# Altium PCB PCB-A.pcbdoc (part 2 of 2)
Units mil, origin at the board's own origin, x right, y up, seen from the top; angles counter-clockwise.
Board outline 4955 x 3850 mil, 4 copper layers (Top Layer, Inner1, Inner2, Bottom Layer); 128 components, 159 nets, 685 pads, 359 vias.
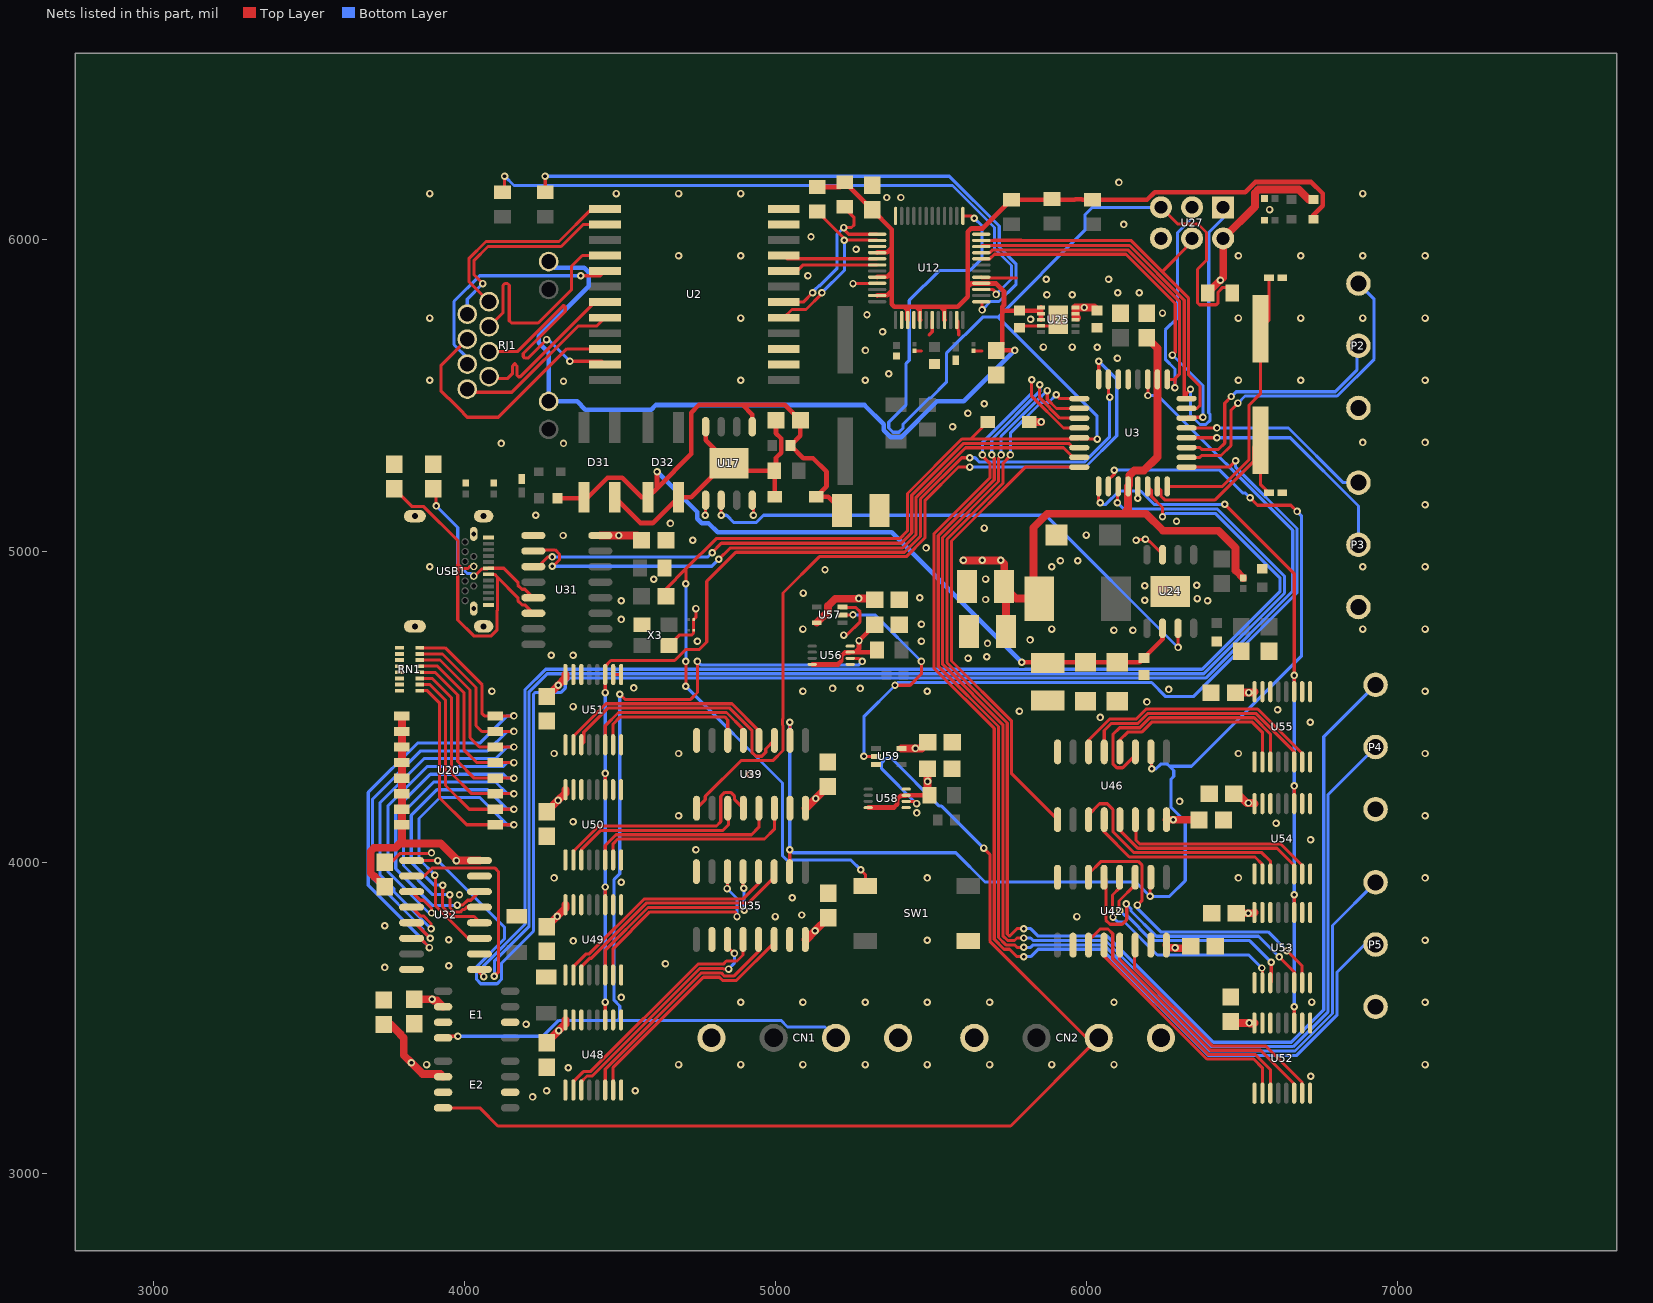
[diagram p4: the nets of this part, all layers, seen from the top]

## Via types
v1: diameter 24, hole 12, Top Layer to Bottom Layer, 345 vias
v2: diameter 24.02, hole 12.01, Top Layer to Bottom Layer, 14 vias

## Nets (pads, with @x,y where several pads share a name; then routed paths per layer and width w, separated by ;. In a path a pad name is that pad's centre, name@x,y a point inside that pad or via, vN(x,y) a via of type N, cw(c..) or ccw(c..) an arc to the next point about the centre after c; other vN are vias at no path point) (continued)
+5V: C25.1 C30.1 C34.2 C60.2 C61.2 C67.2 C78.1 C79.2 C80.2 C81.1 C82.1 C83.1 C84.1 C85.1 C86.2 C87.2 C88.1 C89.1 C90.1 C91.1 C93.1 C94.2 C96.1 C97.2 CN1.4 CN2.4 D35.1 E1.2 E2.2 L2.2 LED5.2 R36.1 R52.2 R69.1 R71.1 U3.4 U3.18 U20.9 U20.10 U20.11 U20.12 U20.13 U20.14 U20.15 U20.16 U25.8 U25.9 U25.10 U27.2 U31.16 U32.16 U35.16 U39.16 U42.16 U46.16 U48.16 U49.16 U50.16 U51.16 U52.16 U53.16 U54.16 U55.16 U56.3 U56.8 U57.5 U58.3 U58.8 U59.5 | length 6394.9
  Top Layer w15: U56.8@5118.98,4635.47 5201.65,4635.47 5212.76,4646.58 5212.76,4662.79 5223.55,4673.58 5239.77,4673.58 U56.3@5241.02,4674.84 5257.23,4674.84 ; U58.8@5298.98,4175.47 5381.65,4175.47 5392.76,4186.58 5392.76,4202.79 5403.55,4213.58 5419.77,4213.58 U58.3@5421.02,4214.84 5421.21,4215.02 R71.1@5496.01,4215.02 ; C93.1@5319.91,4762.74 v1(5269.29,4712.13) 5269.29,4686.9 5257.23,4674.84 ; R69.1@5327.53,4682.11 5320.27,4674.84 5257.23,4674.84
  Top Layer w25: C87.2@3741.36,3477.9 3764.23,3477.9 3794.93,3447.2 3794.93,3445.21 3805.76,3434.37 3805.76,3379.3 v1(3830.48,3354.58) 3866.47,3318.6 3923.53,3318.6 E2.2@3932.13,3310 ; C34.2@3744.79,3920.98 3712.31,3953.47 3710.55,3953.47 3699.72,3964.31 3699.72,4035.14 3710.55,4045.98 3779.03,4045.98 3793.05,4060 ; U20.9@3800,4470 U20.10@3800,4420 U20.11@3800,4370 U20.12@3800,4320 U20.13@3800,4270 U20.14@3800,4220 U20.15@3800,4170 U20.16@3800,4120 3800,4066.95 3793.05,4060 ; C80.2@3840,3559.37 v1(3896.78,3559.37) 3901.46,3554.69 3912.44,3554.69 E1.2@3932.13,3535 ; U32.16@4049.02,4005 v1(3975.01,4005) 3975.01,4010 3925.01,4060 3793.05,4060 ; C81.1@4265,3419.37 v1(4304.08,3458.45) 4325.43,3479.8 U48.16@4325.43,3492.82 ; C82.1@4265.66,3791.9 v1(4299.19,3825.42) 4325.43,3851.66 U49.16@4325.43,3862.82 ; C83.1@4265.66,4162.1 v1(4301.86,4198.3) 4325.43,4221.87 U50.16@4325.43,4232.82 ; C84.1@4265.66,4532.3 v1(4302.09,4568.73) 4325.43,4592.07 U51.16@4325.43,4602.82 ; U31.16@4437.7,5050 v1(4496.56,5050) 4555.42,5050 C30.1@4570.42,5035 ; U35.16@5096.58,3751.35 5100.35,3751.35 v1(5127.95,3778.96) C78.1@5170,3821 ; U39.16@5097.31,4173.26 5099.24,4173.26 v1(5130.44,4204.47) C79.2@5168.89,4242.91 ; U57.5@5133.66,4769.41 5170,4805.75 5170,4824.04 5192.93,4846.96 5267.79,4846.96 v1(5268.57,4847.74) 5315.21,4847.74 C94.2@5320.21,4842.74 ; U59.5@5406.34,4365.59 v1(5450.87,4365.59) 5471.22,4365.59 C97.2@5490.63,4385 ; C96.1@5489.82,4300.66 v1(5489.82,4259.21) 5489.82,4221.22 R71.1@5496.01,4215.02 ; v1(5605,4970) v1(5665.43,4970) v1(5725,4970) 5736.01,4958.99 C61.2@5736.01,4886.37 ; C60.2@5742.09,4741.37 5742.09,4880.29 5775.25,4847.13 L2.2@5849.15,4847.13 5830,4866.28 5830,5075 5875,5120 6120.69,5120 ; D35.1@5816.93,5415 v1(5855,5415) ; 5970,5750 5965.57,5754.43 U25.9@5965.57,5763.24 U25.10@5965.57,5782.93 v1(5993.68,5782.93) 6024.96,5782.93 C67.2@6035,5772.89 ; C25.1@6195,5685.63 6228.74,5651.89 U3.18@6228.74,5552 6228.74,5302.49 6185.23,5258.98 6154.42,5258.98 6138.39,5242.95 6138.39,5212.14 U3.4@6134.25,5208 6134.25,5133.57 6120.69,5120 ; U42.16@6257.31,3733.26 6266.01,3724.56 v1(6285.5,3724.56) 6287.05,3723.02 6328.65,3723.02 C85.1@6335.63,3730 ; U46.16@6257.68,4136.35 v1(6279.77,4136.35) 6361.46,4136.35 C86.2@6362.44,4135.37 ; R36.1@6390.63,5830 v1(6431.14,5870.51) 6440,5879.37 U27.2@6440,6005 6542.6,6107.6 6542.6,6151.46 6553.43,6162.3 6683.11,6162.3 6715.39,6130.02 LED5.2@6730.57,6130.02 ; C91.1@6474.37,4220 6486.29,4220 v1@6516.29,4190 ; C88.1@6479.11,3481.65 6480.29,3482.82 v1(6523.66,3482.82) 6525.72,3480.76 6538.37,3480.76 U52.16@6540.43,3482.82 ; C90.1@6479.37,4545 v1(6522.05,4545) 6537.6,4545 U55.16@6540.43,4547.82 ; C89.1@6482.4,3835.37 v1(6520.72,3835.37) 6537.98,3835.37 U53.16@6540.43,3837.82 ; R52.2@6504.78,4913.09 6480.07,4937.8 6480.07,5009.79 6424.86,5065 6246.87,5065 6191.87,5120 6120.69,5120 ; v1(6521.29,4190) 6538.26,4190 U54.16@6540.43,4187.82
+33V: C32.1 C33.1 C66.2 LED6.2 R38.2 R39.2 R40.2 R60.2 R61.2 RJ1.9 RJ1.11 U12.4 U12.8 U12.11 U12.15 U12.17 U12.21 U12.28 U25.1 U25.2 U25.3 | length 5527.4
  Top Layer w15: R60.2@5134.87,6170.49 5208.47,6170.49 R61.2@5223.47,6185.49 5311.55,6097.42 C33.1@5311.55,6097.22 5375,6033.76 5375,5975.4 ; U12.11@5327.68,5821.42 5328.55,5822.28 5359.69,5822.28 5375,5837.6 ; U12.8@5327.68,5880.47 5328.56,5881.35 5359.69,5881.35 5375,5896.66 ; U12.4@5327.68,5959.21 5328.56,5960.09 5359.69,5960.09 5375,5975.4 ; U12.15@5426.1,5742.68 5425.23,5743.55 5425.23,5774.69 5414.21,5785.71 ; U12.17@5465.47,5742.68 5464.6,5743.55 5464.6,5774.69 5453.58,5785.71 ; U12.21@5544.21,5742.68 5543.35,5743.55 5543.35,5774.69 5532.32,5785.71 ; U12.28@5662.32,5860.79 U12.28@5661.44,5859.91 ; C32.1@5710,5644.37 C32.1@5710.63,5645 ; v1(5770,5645) C32.1@5710.63,5645 ; U25.3@5854.43,5743.56 U25.2@5854.43,5763.24 U25.1@5854.43,5782.93 5844.39,5772.89 C66.2@5785,5772.89 5730,5772.89 ; LED6.2@6730.57,6066.15 6730.57,6081.4 6759.82,6110.65 6759.82,6149.39 6722.91,6186.3 6543.49,6186.3 6511.13,6153.93 6219.73,6153.93 6195.17,6129.37 R40.2@6020,6129.37 5986.93,6129.37 5985.47,6130.83 5964.34,6130.83 5962.88,6129.37 5759.37,6129.37 R38.2@5759.25,6129.25 5667.08,6037.09 5630.31,6037.09 5619.29,6026.06 5619.29,5848.89 ; 5375,5837.6 5375,5896.66 ; 5375,5837.6 5375,5793.78 5383.07,5785.71 5414.21,5785.71 ; 5375,5896.66 5375,5975.4 ; 5414.21,5785.71 5453.58,5785.71 ; 5453.58,5785.71 5532.32,5785.71 ; 5532.32,5785.71 5587.24,5785.71 5619.29,5817.76 5619.29,5848.89 ; 5619.29,5848.89 5630.31,5859.91 U12.28@5661.44,5859.91 ; U12.28@5661.44,5859.91 5710.99,5859.91 5735.35,5835.56 5735.35,5790.9 5730,5785.55 5730,5772.89 ; C32.1@5710.63,5645 5730,5664.37 5730,5772.89
  Bottom Layer w15: RJ1.9@4271.77,5930.67 4291.93,5910.51 4385.57,5910.51 4400.51,5895.57 4400.51,5851.58 4239.49,5690.57 4239.49,5669.43 4271.76,5637.16 RJ1.11@4271.77,5481.07 4362.87,5481.07 4389.44,5454.5 4601.34,5454.5 4616.28,5469.44 5286.8,5469.44 5348.54,5407.69 5348.54,5388.64 5371.68,5365.5 5404.4,5365.5 5519.97,5481.07 5606.07,5481.07 v1(5770,5645)
A0: U3.23 U48.11 U49.11 U50.11 U51.11 | length 3555.6
  Top Layer w10: U48.11@4453.39,3492.82 v1(4453.39,3550) ; U49.11@4453.39,3862.82 v1(4453.39,3920) ; U50.11@4453.39,4232.82 v1(4453.39,4285) ; v1(4453.39,4545) U51.11@4453.39,4602.82 4453.39,4629.67 4471.63,4647.91 4676.42,4647.91 4711.8,4683.29 4755.82,4683.29 4780,4707.47 4780,4902.52 4873.48,4996 5415.4,4996 5467,5047.6 5467,5167.6 5599.4,5300 v1(5625,5300) ; U3.23@6071.26,5552 6071.26,5498.74 v1(6075,5495)
  Bottom Layer w10: v1(4453.39,3550) v1(4453.39,3920) v1(4453.39,4285) v1(4453.39,4545) ; v1(5625,5300) 5642.47,5300 5656.47,5286 5993.53,5286 6075,5367.47 v1(6075,5495)
A1: U3.24 U39.9 | length 2542.3
  Top Layer w10: U39.9@4747.31,4173.26 4775.01,4200.96 4775.01,4211.32 4889.87,4326.18 4992.54,4326.18 5025,4358.64 5025,4439.05 5023.58,4440.47 5023.58,4459.53 5025,4460.95 5025,4865 5142,4982 5421.2,4982 5481,5041.8 5481,5161.8 5589.2,5270 v1(5625,5270) ; U3.24@6039.76,5552 6040,5552.24 v1(6040,5610)
  Bottom Layer w10: v1(5625,5270) 5997.33,5270 6098,5370.67 6098,5552 v1(6040,5610)
A2: P4.3 U3.25 | length 4391
  Top Layer w10: v1(5756,5309) 5756,5306.47 5732,5282.47 5732,5217.6 5552,5037.6 5552,4641.33 5745.93,4447.4 5745.93,3769.07 5753,3762 5777,3786 v1(5799,3786) ; v1(5903,5502.06) 5915.05,5490 5977.26,5490 U3.25@5977.5,5490.24
  Bottom Layer w10: v1(5756,5309) 5756,5379 5854.48,5477.48 5878.42,5477.48 v1(5903,5502.06) ; v1(5799,3786) 5821,3786 5845,3762 6067.4,3762 6408.57,3420.83 6659.17,3420.83 6763.34,3525 6763.34,4403.34 P4.3@6930,4570
A3: P4.2 U3.26 | length 4277.4
  Top Layer w10: v1(5726,5309) 5726,5306.47 5718,5298.47 5718,5223.4 5538,5043.4 5538,4635.53 5731.93,4441.6 5731.93,3763.27 5747.2,3748 5769,3748 5777,3756 v1(5799,3756) ; v1(5874.56,5516.04) 5874.56,5487.57 5904.07,5458.06 5944.91,5458.06 5945.59,5458.74 U3.26@5977.5,5458.74
  Bottom Layer w10: v1(5726,5309) 5726,5368.8 5848.68,5491.48 5850.1,5491.48 5863.57,5504.96 5863.57,5505.06 v1(5874.56,5516.04) ; v1(5799,3756) 5821,3756 5829,3748 6061.6,3748 6402.77,3406.83 6664.97,3406.83 6777.34,3519.2 6777.34,3731.6 ; 6777.4,3731.66 6777.4,4217.4 P4.2@6930,4370
A4: P5.3 U3.27 | length 3956.1
  Top Layer w10: v1(5696,5309) 5696,5306.47 5704,5298.47 5704,5229.2 5524,5049.2 5524,4629.73 5717.93,4435.8 5717.93,3757.47 5741.4,3734 5769,3734 5777,3726 v1(5799,3726) ; v1(5850.57,5534.48) 5850,5533.91 5850,5492.33 5915.08,5427.24 U3.27@5977.5,5427.24
  Bottom Layer w10: v1(5696,5309) 5696,5358.6 5850.57,5513.17 v1(5850.57,5534.48) ; v1(5799,3726) 5821,3726 5829,3734 6055.8,3734 6396.97,3392.83 6670.77,3392.83 6791.34,3513.4 6791.34,3725.8 ; 6791.4,3725.86 6791.4,3796.4 P5.3@6930,3935
A5: P5.2 U3.28 | length 3906.1
  Top Layer w10: v1(5666,5309) 5666,5306.47 5690,5282.47 5690,5235 5510,5055 5510,4623.93 5703.93,4430 5703.93,3751.67 5735.6,3720 5753,3720 5777,3696 v1(5799,3696) ; v1(5824.36,5550.7) 5824.36,5498.17 5926.78,5395.75 U3.28@5977.5,5395.75
  Bottom Layer w10: v1(5666,5309) 5666,5348.4 5824.36,5506.75 v1(5824.36,5550.7) ; v1(5799,3696) 5821,3696 5845,3720 6050,3720 6391.17,3378.83 6676.57,3378.83 6805.34,3507.6 6805.34,3645.34 6895,3735 P5.2@6930,3735
A6: U3.19 U32.1 | length 5125.3
  Top Layer w10: U32.1@3830.98,4005 v1(3915,4005) ; U3.19@6197.24,5552 6198.24,5551 v1(6198.24,5500)
  Bottom Layer w10: v1(3915,4005) 4130,3790 4130,3754.17 4039.91,3664.08 4039.91,3622.47 4053.39,3609 4105.8,3609 4120.23,3623.42 4120.23,3675.23 4223,3778 4223,4540 4228.73,4545.73 4311.61,4545.73 4325.09,4559.2 4325.09,4578.25 4338.33,4591.5 6383.62,4591.5 6663.56,4871.44 6663.56,5066.44 6230,5500 v1(6198.24,5500)
A7: U3.22
ACT0A: CN1.3 E1.4 U56.2 | length 3324
  Top Layer w10: E1.4@3932.13,3435 3937.13,3440 v1(3980,3440) ; v1(4500,4540) 4516.93,4523.07 4728.07,4523.07 4750,4545 v1(4750,4645) ; U56.2@5241.02,4655.16 5269.84,4655.16 v1(5280,4645)
  Bottom Layer w10: v1(3980,3440) 4253.1,3440 4304.38,3491.28 4494,3491.28 ; v1(4500,4540) 4500,3962.53 4482,3944.53 4482,3555.47 4500,3537.47 4500,3497.28 4494,3491.28 ; v1(4750,4645) 4761,4634 5269,4634 v1(5280,4645) ; CN1.3@5195,3435 5160,3470 5039.59,3470 5018.31,3491.28 4494,3491.28
ACT0D0: U35.11 U48.3 | length 763.7
  Top Layer w10: U48.3@4376.61,3267.18 4376.61,3294.01 4394.86,3312.26 4411.64,3312.26 4757.38,3658 4831.8,3658 4833.56,3656.23 v1(4849.84,3656.23) ; U35.11@4846.58,3751.35 4846.58,3728.42 v1(4868.74,3706.26)
  Bottom Layer w10: v1(4849.84,3656.23) 4868.74,3675.13 v1(4868.74,3706.26)
ACT0D1: U35.12 U48.2 | length 791
  Top Layer w10: U48.2@4351.02,3267.18 4351.02,3294.02 4383.26,3326.26 4405.84,3326.26 4751.58,3672 4833.08,3672 4843.08,3682 4877,3682 4896.58,3701.58 U35.12@4896.58,3751.35
ACT0D2: U35.13 U48.6 | length 764
  Top Layer w10: U48.6@4453.39,3267.18 4453.39,3334.21 4763.18,3644 4826,3644 4836.77,3633.23 4866.2,3633.23 4946.58,3713.61 U35.13@4946.58,3751.35
ACT0D3: U35.14 U48.7 | length 775.8
  Top Layer w10: U48.7@4478.98,3267.18 4478.98,3340 4768.98,3630 4820.2,3630 4830.97,3619.23 4874.82,3619.23 4996.58,3741 U35.14@4996.58,3751.35
ACT0D4: U35.3 U49.3 | length 783.7
  Top Layer w10: U49.3@4376.61,3637.18 4376.61,3664.01 4403.6,3691 4408.4,3691 4585.4,3868 4913,3868 4996.58,3951.58 U35.3@4996.58,3969.39
ACT0D5: U35.4 U49.2 | length 771
  Top Layer w10: U49.2@4351.02,3637.18 4351.02,3664.02 4392,3705 4402.6,3705 4579.6,3882 4897,3882 4946.58,3931.58 U35.4@4946.58,3969.39
ACT0D6: U35.5 U49.6 | length 712.2
  Top Layer w10: U49.6@4453.39,3637.18 4453.39,3716.19 4591.2,3854 4891,3854 v1(4900,3845) ; U35.5@4896.58,3969.39 4896.58,3918.42 v1(4898.74,3916.26)
  Bottom Layer w10: v1(4898.74,3916.26) 4900,3915 v1(4900,3845)
ACT0D7: U35.6 U49.7 | length 701
  Top Layer w10: U49.7@4478.98,3637.18 4478.98,3721.98 4597,3840 4870,3840 4877.07,3832.93 v1(4877.07,3825) ; v1(4845,3915) 4846.58,3916.58 U35.6@4846.58,3969.39
  Bottom Layer w10: v1(4845,3915) 4877.07,3882.93 4877.07,3854.6 4877,3854.53 4877,3835.47 4877.07,3835.4 v1(4877.07,3825)
ACT0D8: U39.11 U50.3 | length 599
  Top Layer w10: U50.3@4376.61,4007.18 4376.61,4039.75 4438.93,4102.07 4832.07,4102.07 4850,4120 4850,4175.95 U39.11@4847.31,4173.26
ACT0D9: U39.12 U50.2 | length 726.9
  Top Layer w10: U50.2@4351.02,4007.18 4351.02,4034.02 4433.07,4116.07 4811.07,4116.07 4825.01,4130.01 4825.01,4211.32 4838.07,4224.38 4856.54,4224.38 4869.61,4211.32 4869.61,4200.96 U39.12@4897.31,4173.26
ACT0D10: U39.13 U50.6 | length 625.8
  Top Layer w10: U50.6@4453.39,4007.18 4453.39,4053.19 4488.27,4088.07 4923.83,4088.07 4947.31,4111.55 U39.13@4947.31,4173.26
ACT0D11: U39.14 U50.7 | length 657
  Top Layer w10: U50.7@4478.98,4007.18 4478.98,4058.98 4494.07,4074.07 4965.63,4074.07 4997.31,4105.75 U39.14@4997.31,4173.26
ACT0D12: U39.3 U51.3 | length 821.5
  Top Layer w10: U51.3@4376.61,4377.18 4384.46,4385.02 4384.46,4417.66 4461.87,4495.07 4853.89,4495.07 4925,4423.96 4925.01,4353.25 4938.07,4340.18 4956.54,4340.18 4969.61,4353.25 4969.61,4363.6 U39.3@4997.31,4391.3
ACT0D13: U39.4 U51.2 | length 733.8
  Top Layer w10: U51.2@4351.02,4377.18 4351.02,4404.02 4456.07,4509.07 4860.93,4509.07 4947.31,4422.69 U39.4@4947.31,4391.3
ACT0D14: U39.5 U51.6 | length 580.7
  Top Layer w10: U51.6@4453.39,4377.18 4453.39,4438.19 4496.27,4481.07 4843.11,4481.07 4897.31,4426.87 U39.5@4897.31,4391.3
ACT0D15: U39.6 U51.7 | length 514.6
  Top Layer w10: U51.7@4478.98,4377.18 4478.98,4443.98 4502.07,4467.07 4837.31,4467.07 4847.31,4457.07 U39.6@4847.31,4391.3
ACT1A: CN2.3 E2.4 U58.2 | length 3702.5
  Top Layer w10: E2.4@3932.13,3210 4050,3210 4108.2,3151.8 5756.8,3151.8 CN2.3@6040,3435 6033.47,3441.53 5994.28,3441.53 5689.93,3745.88 5689.93,4025.07 v1(5670,4045) ; U58.2@5421.02,4195.16 5447.31,4195.16 v1(5454.33,4188.14)
  Bottom Layer w10: v1(5454.33,4188.14) 5342,4300.47 5342,4319.53 5355.47,4333 5374.53,4333 5527.53,4180 5535,4180 v1(5670,4045)
ACT1CLR: U3.1 U52.11 U53.11 U54.11 U55.11 | length 2419.1
  Top Layer w10: U3.1@6039.76,5208 6039.76,5160.24 v1(6045,5155) ; v1(6445,5150) 6668.39,4926.61 v1(6668.39,4600) U55.11@6668.39,4547.82 ; U52.11@6668.39,3482.82 v1(6668.39,3535) ; U53.11@6668.39,3837.82 v1(6668.39,3895) ; U54.11@6668.39,4187.82 v1(6668.39,4245)
  Bottom Layer w10: v1(6045,5155) 6050,5150 6062.47,5150 6105.47,5193 6174.53,5193 6217.53,5150 v1(6445,5150) ; v1(6668.39,3535) v1(6668.39,3895) v1(6668.39,4245) v1(6668.39,4600)
ACT1D0: U42.11 U52.3 | length 924.3
  Top Layer w10: U42.11@6007.31,3733.26 6007.31,3747.31 6045,3785 6070,3785 6085,3770 6085,3689.38 6393.31,3381.07 6543.73,3381.07 6591.61,3333.19 U52.3@6591.61,3257.18
ACT1D1: U42.12 U52.2 | length 774.9
  Top Layer w10: U42.12@6057.31,3733.26 6057.31,3697.28 6387.51,3367.07 6537.93,3367.07 6566.02,3338.98 U52.2@6566.02,3257.18
ACT1D2: U42.13 U52.6 | length 802.7
  Top Layer w10: U42.13@6107.31,3733.26 6107.31,3686.88 6399.11,3395.07 6559.93,3395.07 6668.39,3286.61 U52.6@6668.39,3257.18
ACT1D3: U42.14 U52.7 | length 801
  Top Layer w10: U42.14@6157.31,3733.26 6154.7,3730.65 6154.7,3659.28 6404.91,3409.07 6576.35,3409.07 6693.98,3291.44 U52.7@6693.98,3257.18
ACT1D4: U42.3 U53.3 | length 752.8
  Top Layer w10: v1(6107.02,3844.34) 6107.02,3854.24 6105.23,3856.03 6105.23,3875.08 6157.31,3927.16 U42.3@6157.31,3951.3 ; U53.3@6591.61,3612.18 6594.59,3615.16 v1(6594.59,3677.98)
  Bottom Layer w10: v1(6107.02,3844.34) 6122.57,3828.79 6129.64,3828.79 6210.87,3747.56 6525.01,3747.56 v1(6594.59,3677.98)
ACT1D5: U42.4 U53.2 | length 733.1
  Top Layer w10: v1(6085.8,3823.13) 6085.8,3833.03 6084.02,3834.82 6084.02,3894.02 6107.31,3917.31 U42.4@6107.31,3951.3 ; v1(6564.59,3659.59) 6566.02,3658.16 U53.2@6566.02,3612.18
  Bottom Layer w10: v1(6085.8,3823.13) 6101.36,3807.57 6122.57,3807.57 6228.58,3701.56 6522.62,3701.56 v1(6564.59,3659.59)
ACT1D6: U42.5 U53.6 | length 939.6
  Top Layer w10: U42.5@6057.31,3951.3 6062.8,3945.8 6062.8,3813.6 6076.28,3800.13 6115.13,3800.13 6130.02,3815.02 6130.02,3853.87 6128.23,3855.66 v1(6128.23,3865.56) ; v1(6620,3695) 6668.39,3646.61 U53.6@6668.39,3612.18
  Bottom Layer w10: v1(6128.23,3865.56) 6143.79,3850 6143.79,3842.93 6225.15,3761.56 6553.44,3761.56 v1(6620,3695)
ACT1D7: U42.6 U53.7 | length 1009.8
  Top Layer w10: U42.6@6007.31,3951.3 6007.31,3961.66 6048.07,4002.42 6166.54,4002.42 6179.61,3989.36 6179.61,3876.93 v1(6164.49,3861.82) ; v1(6645,3715) 6693.98,3666.02 U53.7@6693.98,3612.18
  Bottom Layer w10: v1(6164.49,3861.82) 6165,3861.31 6165,3850 6239.44,3775.56 6584.44,3775.56 v1(6645,3715)
ACT1D8: U46.11 U54.3 | length 773.9
  Top Layer w10: U46.11@6007.68,4136.35 6007.68,4152.68 6042.47,4187.47 6067.53,4187.47 6085.39,4169.61 6085.39,4098.3 6153.26,4030.42 6564.6,4030.42 6591.61,4003.41 U54.3@6591.61,3962.18
ACT1D9: U46.12 U54.2 | length 621.3
  Top Layer w10: U46.12@6057.68,4136.35 6057.68,4097.32 6138.58,4016.42 6542.4,4016.42 6566.02,3992.8 U54.2@6566.02,3962.18
ACT1D10: U46.13 U54.6 | length 668.5
  Top Layer w10: U46.13@6107.68,4136.35 6107.68,4102.42 6165.69,4044.42 6612.99,4044.42 6668.39,3989.02 U54.6@6668.39,3962.18
ACT1D11: U46.14 U54.7 | length 661.7
  Top Layer w10: U46.14@6157.68,4136.35 6160,4134.04 6160,4070 6171.58,4058.42 6624.58,4058.42 6693.98,3989.02 U54.7@6693.98,3962.18
ACT1D12: U46.3 U55.3 | length 838.7
  Top Layer w10: U46.3@6157.68,4354.39 6157.68,4344.04 6116.92,4303.27 6098.45,4303.27 6085.39,4316.34 6085.39,4410.39 6107,4432 6172.2,4432 6204.2,4464 6539.4,4464 6591.61,4411.79 U55.3@6591.61,4322.18
ACT1D13: U46.4 U55.2 | length 629.2
  Top Layer w10: U46.4@6107.68,4354.39 6107.68,4392.68 6133,4418 6178,4418 6210,4450 6533.61,4450 6565.99,4417.61 U55.2@6566.02,4322.18
ACT1D14: U46.5 U55.6 | length 785.7
  Top Layer w10: U46.5@6057.68,4354.39 6057.68,4422.89 6080.8,4446 6166.4,4446 6198.4,4478 6545.2,4478 6668.39,4354.81 U55.6@6668.39,4322.18
ACT1D15: U46.6 U55.7 | length 851.8
  Top Layer w10: U46.6@6007.68,4354.39 6007.68,4392.68 6075,4460 6160.6,4460 6192.6,4492 6551,4492 6693.98,4349.02 U55.7@6693.98,4322.18
ACT1RD: U3.32 U46.9 | length 1546.6
  Top Layer w10: U46.9@5907.68,4136.35 5759.93,4284.11 5759.93,4453.2 5566.56,4646.56 5566.56,5032.37 5803.96,5269.76 U3.32@5977.5,5269.76
ACTCLK: U3.2 U35.2 U39.2 U42.2 U46.2 | length 4219.5
  Top Layer w10: U35.2@5046.58,3969.39 v1(5046.58,4040) ; v1(5046.58,4450) 5047.31,4449.27 U39.2@5047.31,4391.3 ; U3.2@6071.26,5208 6070,5209.26 6070,5226.95 6090,5246.95 v1(6090,5260) ; v1(6205,3890) 6205,3948.99 U42.2@6207.31,3951.3 ; U46.2@6207.68,4354.39 6210,4352.08 v1(6210,4300) ; v1(6526.46,5171.02) 6550.34,5147.13 6657.82,5147.13 v1(6677.48,5127.48)
  Bottom Layer w10: v1(5046.58,4450) v1(5046.58,4040) 5056.58,4030 5580.2,4030 5674.2,3936 6159,3936 v1(6205,3890) 6267.53,3890 6318,3940.47 6318,4130.65 6272.21,4176.44 6272.21,4266.47 6281.21,4275.47 6281.21,4294.53 6267.73,4308 ; v1(6090,5260) 6429.15,5260 6502.57,5186.57 6510.9,5186.57 v1(6526.46,5171.02) ; v1(6210,4300) 6224.14,4300 6239.14,4315 6260.73,4315 6267.73,4308 ; v1(6677.48,5127.48) 6691.39,5113.57 6691.39,5090.76 6691.56,5090.58 6691.56,4661.56 6338,4308 6267.73,4308
ACTLD: U3.9 U57.2 U59.2 | length 2889.9
  Top Layer w10: U57.2@5216.34,4795 v1(5250,4795) ; v1(5285,4340) U59.2@5323.66,4340 ; v1(5385,4568.5) 5433.5,4568.5 5470,4605 v1(5470,4645) ; U3.9@6322.5,5269.76 6459.76,5269.76 v1(6480,5290)
  Bottom Layer w10: v1(5250,4795) 5320,4795 v1(5470,4645) ; v1(5285,4340) 5285,4467.5 5385,4567.5 v1(5385,4568.5) 5394,4577.5 6209.97,4577.5 6255.47,4532 6343.92,4532 6677.56,4865.64 6677.56,5072.24 6480,5269.8 v1(6480,5290)
ACTLED: U12.27 U28.1 | length 2013.2
  Top Layer w10: U28.1@4123.18,6153.31 4130,6160.14 v1(4130,6205) ; U12.27@5662.32,5841.1 5698.9,5841.1 5709.85,5830.15 v1(5709.85,5825)
  Bottom Layer w10: v1(4130,6205) 4160,6175 5570,6175 5705,6040 5705,5972.58 5759.5,5918.08 5759.5,5874.7 5735.33,5850.53 ; v1(5709.85,5825) 5735.33,5850.48
AGND: C23.1 C25.2 C26.1 C28.1 C29.1 C30.2 C32.2 C33.2 C34.1 C45.2 C46.1 C60.1 C61.1 C63.1 C64.1 C66.1 C67.1 C68.1 C69.1 C70.1 C71.1 C72.1 C73.1 C75.1 C76.1 C77.1 C78.2 C79.1 C80.1 C81.2 C82.2 C83.2 C84.2 C85.2 C86.1 C87.1 C88.2 C89.2 C90.2 C91.2 C93.2 C94.1 C96.2 C97.1 CN1.1 CN2.1 D33.2 E1.3 E1.6 E2.3 E2.6 P2.1 P3.1 P4.1 P5.1 R33.1 R53.1 R54.2 R55.2 R63.2 R67.1 R68.1 R78.1 R79.1 RN1.1 RN1.2 RN1.3 RN1.4 RN1.5 RN1.6 RN1.7 RN1.8 SW1.1 U3.5 U3.21 U6.1 U12.3 U12.9 U12.14 U12.16 U12.19 U12.23 U12.29 U12.48 U14.1 U17.5 U17.8 U24.7 U24.9 U25.4 U25.11 U26.1 U27.6 U31.1 U32.8 U32.10 U32.15 U35.8 U35.10 U35.15 U39.8 U39.15 U42.8 U42.10 U42.15 U46.8 U46.15 U48.1 U48.8 U48.9 U48.10 U48.14 U48.15 U49.1 U49.8 U49.9 U49.10 U49.14 U49.15 U50.1 U50.8 U50.9 U50.10 U50.14 U50.15 U51.1 U51.8 U51.9 U51.10 U51.14 U51.15 U52.1 U52.8 U52.9 U52.10 U52.14 U52.15 U53.1 U53.8 U53.9 U53.10 U53.14 U53.15 U54.1 U54.8 U54.9 U54.10 U54.14 U54.15 U55.1 U55.8 U55.9 U55.10 U55.14 U55.15 U56.1 U56.4 U57.3 U58.1 U58.4 U59.3 USB1.25 USB1.26 USB1.27 USB1.28 USB1.A1 USB1.A12 USB1.B1 USB1.B12 X3.2 X3.4 | length 1220.3
  Top Layer w10: C34.1@3744.79,3999.72 3765.35,3999.72 3792.92,4027.3 3892.8,4027.3 v1(3895,4029.5) ; U51.10@4478.98,4602.82 U51.9@4504.57,4602.82 ; X3.2@4658.31,4696.53 4691.44,4729.67 4731.01,4729.67 4737.45,4736.11 4737.45,4775.68 4737.68,4775.9 C75.1@4737.68,4780 4745,4787.32 v1(4745,4815) ; v1(4775,5115) 4776.2,5116.2 U17.5@4776.2,5163.62 ; U17.8@4926.2,5163.62 4930,5159.81 v1(4930,5115) ; U57.3@5216.34,4820.59 5218.93,4818 5259.53,4818 5273,4804.53 5273,4773 5230,4730 v1(5220,4730) ; v1(5250,5860) 5326.89,5860 U12.9@5327.68,5860.79 ; U14.1@5447.13,5643.27 5470,5643.27 ; 5495,5695 5504.84,5704.84 U12.19@5504.84,5742.68 ; U12.23@5583.58,5742.68 5586.95,5739.31 5586.95,5711.71 5590,5708.66 5590,5695 ; U6.1@5636.93,5643.27 5665,5643.27 ; U12.29@5662.32,5880.47 5665.5,5877.29 5776.24,5877.29 ; C66.1@5785,5717.77 5791.1,5723.87 U25.4@5854.43,5723.87 5890.31,5723.87 U25.11@5910,5743.56 ; v1(6160,5035) 6162.61,5037.61 v1(6190.08,5037.61) 6195.51,5037.61 6202.51,5030.61 6204.45,5030.61 6245,4990.06 U24.7@6245,4988.11
  other v1: 4220,3245 4265,3265 4550,3265 6721.25,3311.19 4335,3338.91 3879.1,3349.1 4689.1,3349.1 4889.1,3349.1 5089.1,3349.1 5289.1,3349.1 5489.1,3349.1 5689.1,3349.1 5889.1,3349.1 6089.1,3349.1 7089.1,3349.1 4199.1,3479.1 4889.1,3549.1 5089.1,3549.1 5289.1,3549.1 5489.1,3549.1 5689.1,3549.1 6089.1,3549.1 7089.1,3549.1 6725,3550 4505,3565 3745,3661.24 3950,3667.13 4646.9,3672.85 4351.02,3746.68 5489.1,3749.1 7089.1,3749.1 3950,3750 3745,3795 5000,3825 5970,3825 5085,3830 5055,3885 3985,3895 4505,3935 4289.1,3949.1 5489.1,3949.1 6489.1,3949.1 7089.1,3949.1 4745,4040 6720.96,4071.68 6610,4125 4350,4130 4689.1,4149.1 7089.1,4149.1 5455.1,4158.15 6300,4195 4917.88,4282.28 4289.1,4349.1 4689.1,4349.1 6489.1,4349.1 7089.1,4349.1 6720,4450 6045,4465 5785,4485 6615,4490 4350,4500 6195,4515 4089.1,4549.1 5089.1,4549.1 5489.1,4549.1 7089.1,4549.1 6265,4555 5184.4,4558.33 5273.26,4558.33 4545,4560 5620,4655 5680,4660 4280.05,4665 4350,4665 5682.35,4702.9 4750,4710 5470,4710 5819.22,4714.21 6088.83,4745 6150,4745 5089.1,4749.1 5889.1,4749.1 6889.1,4749.1 7089.1,4749.1 5470,4765 4505,4780.12 4505,4840 6390,4840 6187.85,4841.61 5676.27,4844.21 6357.01,4847.13 5465,4850 5090,4865 6187.85,4888.68 6355,4890 4609.79,4909.07 5676.27,4909.95 5160,4940 3889.1,4949.1 5889.1,4949.1 6889.1,4949.1 7089.1,4949.1 5916.86,4969.16 5972.3,4969.16 5485,5010 4735,5035 4317.91,5050 5999.79,5051.37 5671.61,5073.73 4662.99,5088.68 6290,5095.5 4230,5115 7089.1,5149.1 6165,5170 4119.37,5345.91 4319.37,5345.91 6889.1,5349.1 7089.1,5349.1 5570,5400 5619.55,5442.58 5671.61,5473.73 4319.37,5545.91 3889.1,5549.1 4889.1,5549.1 5289.1,5549.1 6489.1,5549.1 6689.1,5549.1 7089.1,5549.1 5365,5570 6100,5620 5290,5645 6035,5655 5862.27,5655.89 5954.52,5655.89 5345,5705 5820.95,5745.03 3889.1,5749.1 4889.1,5749.1 6489.1,5749.1 6689.1,5749.1 6889.1,5749.1 7089.1,5749.1 5295,5760 6245,5765 5873.57,5824.2 5954.52,5824.2 6101.27,5830 6170,5830 5871.61,5873.73 6071.61,5873.73 5105,5885 4689.1,5949.1 4889.1,5949.1 6489.1,5949.1 6689.1,5949.1 6889.1,5949.1 7089.1,5949.1 5260,5970 5115,6010 6120,6050 6589.27,6097.78 5358.88,6136.59 5404.02,6136.59 3889.1,6149.1 4489.1,6149.1 4689.1,6149.1 4889.1,6149.1 6889.1,6149.1 6105,6185
CDB: U17.6 U24.3 | length 1774.4
  Top Layer w10: v1(4826.2,5115) U17.6@4826.2,5163.62 ; v1(6295,4690) U24.3@6295,4751.89
  Bottom Layer w10: v1(4826.2,5115) 4843.67,5115 4866.67,5092 4939.53,5092 4962.53,5115 5870,5115 v1(6295,4690)
D0: U3.30 U31.3 | length 1995.5
  Top Layer w10: U31.3@4222.3,4950 4237.9,4950 4268.86,4980.96 v1(4283,4980.96) ; v1(4797.17,4994.64) 4797.17,4995.46 4826.72,5025 5404.8,5025 5439,5059.2 5439,5179.2 5605.8,5346 5944,5346 5957.24,5332.76 U3.30@5977.5,5332.76
  Bottom Layer w10: v1(4283,4980.96) 4783.49,4980.96 v1(4797.17,4994.64)
D1: U3.31 U31.2 | length 2076.8
  Top Layer w10: U31.2@4222.3,5000 4226.26,5003.96 4292.53,5003.96 4306,4990.49 4306,4971.43 4285.53,4950.96 v1(4283,4950.96) ; v1(4818.38,4973.43) 4854.95,5010 5409.6,5010 5453,5053.4 5453,5173.4 5611.6,5332 5926.55,5332 5957.29,5301.26 U3.31@5977.5,5301.26
  Bottom Layer w10: v1(4283,4950.96) 4795.91,4950.96 v1(4818.38,4973.43)
D6: P2.3 U3.10 | length 1064.4
  Top Layer w10: U3.10@6322.5,5301.26 6364.98,5301.26 6370.73,5307.01 6433.28,5307.01 6465,5338.72 6465,5452.93 v1(6487.63,5475.56)
  Bottom Layer w10: v1(6487.63,5475.56) 6510.25,5498.18 6806.49,5498.18 6925.37,5617.06 6925.37,5809.63 P2.3@6875,5860
D7: P2.2 U3.11 | length 811.1
  Top Layer w10: U3.11@6322.5,5332.76 6364.98,5332.76 6370.73,5327.01 6425,5327.01 6445,5347.01 6445,5475.36 v1(6466.41,5496.77)
  Bottom Layer w10: v1(6466.41,5496.77) 6481.83,5512.18 6800.7,5512.18 6870,5581.49 6870,5655 P2.2@6875,5660
D8: P3.2 U3.12 | length 768.3
  Top Layer w10: U3.12@6322.5,5364.25 v1(6420,5364.25)
  Bottom Layer w10: v1(6420,5364.25) 6655.75,5364.25 6875,5145 P3.2@6875,5020
D9: P3.3 U3.13 | length 625.3
  Top Layer w10: U3.13@6322.5,5395.75 v1(6420,5395.75)
  Bottom Layer w10: v1(6420,5395.75) 6649.88,5395.75 6825.63,5220 P3.3@6875,5220
DN1: C29.2 U31.6 USB1.A7 USB1.B7 | length 1115.3
  Top Layer w10: C29.2@3775,5200.63 3832.78,5142.85 3870.15,5142.85 3980.29,5032.7 3980.29,4957.05 ; USB1.B7@4030.67,4950.75 4019.61,4950.75 4012.55,4943.69 3993.65,4943.69 3980.29,4957.05 ; USB1.A7@4078.31,4925.16 4097.8,4925.16 4107.03,4915.93 4107.03,4915.27 ; U31.6@4222.3,4800 4195.15,4827.15 4185.89,4827.15 4172.5,4840.53 4172.5,4849.8 4107.03,4915.27 ; 3980.29,4957.05 3979.32,4956.08 3979.32,4778.49 4030.65,4727.15 4087.07,4727.15 4105.05,4745.13 4105.05,4806.5 4107.03,4808.48 4107.03,4915.27
DP1: C28.2 U31.5 USB1.A6 USB1.B6 | length 589.4
  Top Layer w10: C28.2@3901.03,5200.63 3910,5191.66 v1(3910,5145) ; USB1.B6@4030.66,4919.25 4033.22,4919.25 4056.04,4942.07 4075.54,4942.07 USB1.A6@4078.31,4944.84 4127.46,4944.84 4172.5,4899.8 4172.5,4890.53 4185.89,4877.15 4195.15,4877.15 U31.5@4222.3,4850
  Bottom Layer w10: v1(3910,5145) 3979.32,5075.69 3979.32,4958.03 4009.4,4927.94 4021.97,4927.94 USB1.B6@4030.66,4919.25
ETH1A: U2.2
ETH1B: U2.3
ETH2A: R60.1 U2.5 U12.2 | length 590.9
  Top Layer w10: U2.5@5027.4,5750 5053.74,5776.34 5098.85,5776.34 5150,5827.48 v2(5150,5830) ; R60.1@5134.87,6091.76 5222.07,6004.55 v2(5222.07,5999.53) 5326.73,5999.53 U12.2@5327.68,5998.58
  Bottom Layer w10: v2(5150,5830) 5222.07,5902.07 v2(5222.07,5999.53)
ETH2B: R61.1 U2.6 U12.1 | length 585.7
  Top Layer w10: U2.6@5027.4,5800 5090,5800 v2(5120,5830) ; R61.1@5223.47,6106.76 5223.47,6101.76 5253.47,6071.76 5253.47,6048.47 5245,6040 v2(5220,6040) 5220,6034.14 5235.87,6018.27 U12.1@5327.68,6018.27
  Bottom Layer w10: v2(5120,5830) 5126.99,5836.99 5126.99,5839.53 5140.47,5853.01 5143.01,5853.01 5199.06,5909.06 5199.06,6019.06 v2(5220,6040)
ETH3A: U2.8 U12.6 | length 308.6
  Top Layer w10: U2.8@5027.4,5900 5070,5900 5090,5920 5327.52,5920 U12.6@5327.68,5919.84
ETH3B: U2.9 U12.5 | length 304.6
  Top Layer w10: U2.9@5027.4,5950 5037.87,5939.53 U12.5@5327.68,5939.53
ETH4A: U2.11
ETH4B: U2.12
IP0: RN1.9 U20.1 U32.11 | length 1517.6
  Top Layer w10: RN1.9@3857.79,4551.1 3881.57,4551.1 3920.13,4512.54 3920.13,4207.79 4007.92,4120 U20.1@4100,4120 v1(4160,4120) ; v1(3905.9,3957.5) 3907.97,3955.44 3907.97,3859.46 4012.43,3755 U32.11@4049.02,3755
  Bottom Layer w10: v1(3905.9,3957.5) 3907.5,3957.5 3855,4010 3855,4140 3922.5,4207.5 4050.5,4207.5 4138,4120 v1(4160,4120)
IP1: RN1.10 U20.2 U32.12 | length 1512.2
  Top Layer w10: RN1.10@3857.79,4570.79 3889.73,4570.79 3939.82,4520.7 3939.82,4246.26 4016.08,4170 U20.2@4100,4170 v1(4160,4170) ; v1(3930.97,3925.97) 3930.97,3905.43 3930.42,3904.88 3930.42,3856.81 3962.23,3825 4031.93,3825 4049.02,3807.91 U32.12@4049.02,3805
  Bottom Layer w10: v1(3930.97,3925.97) 3903.68,3925.97 3830,3999.64 3830,4150.36 3912.14,4232.5 4075.5,4232.5 4138,4170 v1(4160,4170)
IP2: RN1.11 U20.3 U32.13 | length 1518.1
  Top Layer w10: RN1.11@3857.79,4590.47 3897.88,4590.47 3959.5,4528.85 3959.5,4284.73 4024.23,4220 U20.3@4100,4220 v1(4160,4220) ; v1(3953.42,3895.35) 3954.55,3894.21 3954.55,3852.47 3968.03,3839 3987.08,3839 3996.08,3848 4001.46,3848 4008.46,3855 U32.13@4049.02,3855
  Bottom Layer w10: v1(3953.42,3895.35) 3898.94,3895.35 3805,3989.29 3805,4160.71 3901.79,4257.5 4100.5,4257.5 4138,4220 v1(4160,4220)
IP3: RN1.12 U20.4 U32.14 | length 1535.8
  Top Layer w10: RN1.12@3857.79,4610.16 3906.03,4610.16 3979.19,4537 3979.19,4323.2 4032.38,4270 U20.4@4100,4270 v1(4160,4270) ; v1(3977.55,3862) 3995.67,3862 4010.96,3877.3 4021.32,3877.3 U32.14@4049.02,3905
  Bottom Layer w10: v1(3977.55,3862) 3979.07,3862 3981.07,3860 3898.93,3860 3780,3978.93 3780,4171.07 3891.43,4282.5 4125.5,4282.5 4138,4270 v1(4160,4270)
IP4: RN1.13 U20.5 U32.3 | length 1510.6
  Top Layer w10: U32.3@3830.98,3905 3858.68,3877.3 3869.04,3877.3 3895.19,3851.15 v1(3895.19,3836.42) ; RN1.13@3857.79,4629.84 3914.18,4629.84 3998.87,4545.16 3998.87,4361.67 4040.54,4320 U20.5@4100,4320 v1(4160,4320)
  Bottom Layer w10: v1(3895.19,3836.42) 3893.77,3835 3888.58,3835 3755,3968.58 3755,4181.42 3881.08,4307.5 4125.5,4307.5 4138,4320 v1(4160,4320)
IP5: RN1.14 U20.6 U32.4 | length 1587.2
  Top Layer w10: U32.4@3830.98,3855 3858.68,3827.3 3869.04,3827.3 3893.61,3802.72 v1(3893.61,3785.47) ; RN1.14@3857.79,4649.53 3922.34,4649.53 4018.56,4553.31 4018.56,4400.13 4048.69,4370 U20.6@4100,4370 v1(4160,4370)
  Bottom Layer w10: v1(3893.61,3785.47) 3775,3904.08 3775,3913.22 3730,3958.22 3730,4191.78 3870.72,4332.5 4100.5,4332.5 4138,4370 v1(4160,4370)
IP6: RN1.15 U20.7 U32.5 | length 1626
  Top Layer w10: U32.5@3830.98,3805 3841.29,3805 v1(3890.82,3755.47) ; RN1.15@3857.79,4669.21 3930.49,4669.21 4038.24,4561.46 4038.24,4438.61 4056.84,4420 U20.7@4100,4420 v1(4160,4420)
  Bottom Layer w10: v1(3890.82,3755.47) 3867.87,3778.42 3867.87,3785 3705.8,3947.07 3705.8,4202.93 3860.37,4357.5 4075.5,4357.5 4138,4420 v1(4160,4420)
IP7: RN1.16 U20.8 U32.6 | length 1667.2
  Top Layer w10: U32.6@3830.98,3755 3858.77,3755 v1(3888.42,3725.35) ; RN1.16@3857.79,4688.9 3938.65,4688.9 4057.93,4569.62 4057.93,4477.07 4065,4470 U20.8@4100,4470 v1(4160,4470)
  Bottom Layer w10: v1(3888.42,3725.35) 3857.51,3756.25 3857.51,3760 3691.8,3925.71 3691.8,4224.29 3850.01,4382.5 4050.5,4382.5 4138,4470 v1(4160,4470)
LINKLED: U12.25 U29.1 | length 1959
  Top Layer w10: v1(4260,6204.9) 4260.75,6204.15 U29.1@4260.75,6153.31 ; U12.25@5662.32,5801.73 5665,5799.05 v1(5665,5775)
  Bottom Layer w10: v1(4260,6204.9) 5559.9,6204.9 5720,6044.8 5720,5977.38 5773.5,5923.88 5773.5,5856.13 5719.37,5802 5692,5802 v1(5665,5775)
MISO: U3.16 U12.34 U27.1 | length 1950.6
  Top Layer w10: U12.34@5662.32,5978.9 5665.69,5982.27 6139.3,5982.27 6315,5806.57 6315,5497.74 U3.16@6322.5,5490.24 6322.5,5507.5 v1(6335,5520)
  Bottom Layer w10: v1(6335,5520) 6335,5437.47 6365.47,5407 6384.53,5407 6398,5420.47 6398,5439.53 6393.57,5443.96 6393.57,6024.23 6440,6070.67 U27.1@6440,6105
MOSI: U3.15 U12.35 U27.4 | length 1298
  Top Layer w10: U12.35@5662.32,5998.58 5701.85,5998.58 5702.32,5999.06 5790.9,5999.06 5791.38,5998.58 6142.79,5998.58 6243.73,5897.63 ; U3.15@6322.5,5458.74 6355.98,5458.74 6365.98,5468.74 6365.98,5529.02 6329,5566 6329,5812.37 6243.73,5897.63 ; U27.4@6340,6005 6340,5993.9 6243.73,5897.63
OCTCLK: U3.3 U32.2 | length 4900
  Top Layer w10: U32.2@3830.98,3955 3870.88,3955 3896.38,3980.5 4099.5,3980.5 4110,3970 4110,3645.73 v1(4097.09,3632.82) ; v1(6100,5155) 6100,5205.24 U3.3@6102.76,5208
  Bottom Layer w10: v1(4097.09,3632.82) 4097.09,3681.67 4209,3793.57 4209,4547.49 4267.01,4605.5 6377.83,4605.5 6637,4864.67 6637,4918.85 6420.85,5135 6120,5135 v1(6100,5155)
OCTR: U3.6 U32.9 | length 4197.5
  Top Layer w10: U32.9@4049.02,3655 4045.82,3651.8 4045.82,3646.88 4060.71,3632 v1(4062.91,3632) ; U3.6@6197.24,5208 6208.88,5196.36 6208.88,5176.15 6245,5140.03 v1(6245,5110)
  Bottom Layer w10: v1(4062.91,3632) 4062.91,3667.28 4195,3799.37 4195,4553.28 4261.72,4620 5782.47,4620 5782.97,4619.5 5802.03,4619.5 5802.53,4620 6372.53,4620 6623,4870.47 6623,4913.05 6415.05,5121 6256,5121 v1(6245,5110)
POE+: C59.1 C68.2 C69.2 C70.2 C71.2 C73.2 D31.3 D32.3 D34.1 R45.2 U17.1 U24.2 U33.1 | length 3588.5
  Top Layer w15: U33.1@4299.66,5170 4382.89,5170 D31.3@4385.78,5172.89 4398.1,5172.89 4460.71,5235.5 4507.73,5235.5 4570.34,5172.89 D32.3@4590.78,5172.89 4620,5202.11 ; v1(4620,5255) 4620,5202.11 ; U17.1@4926.2,5399.84 4926.2,5438.8 4895,5470 ; C73.2@5215,5130.26 5170.26,5175 D34.1@5131.93,5175 5165,5208.07 5165,5255 5121.42,5298.58 5090.32,5298.58 R45.2@5049.64,5339.25 5080.94,5370.55 C59.1@5080.94,5420 5030.94,5470 4895,5470 ; v1(5792.5,4642.5) 6099.11,4642.5 C70.2@6099.31,4642.7 6171.59,4642.7 C71.2@6185.08,4656.19 6245,4716.11 U24.2@6245,4751.89 ; 4620,5202.11 4730,5312.11 4730,5445 4755,5470 4895,5470
  Bottom Layer w15: v1(4620,5255) 4749.5,5125.5 4749.5,5104.44 4764.44,5089.5 4785.5,5089.5 4815,5060 5375,5060 v1(5792.5,4642.5)
POE-: C59.2 D31.4 D32.4 D34.2 U17.4 U17.9 U21.1 | length 1047.6
  Top Layer w15: D31.4@4484.22,5172.89 4567.11,5090 4606.33,5090 D32.4@4689.22,5172.89 4729.99,5172.89 4838.83,5281.73 U17.9@4851.2,5281.73 ; U17.4@4776.2,5399.84 4776.2,5356.73 U17.9@4851.2,5281.73 ; D34.2@4998.07,5175 4998.07,5256.64 U21.1@4996.74,5257.97 ; C59.2@5002.2,5420 5002.2,5379.35 5019.7,5361.85 5019.7,5316.65 5002.2,5299.16 5002.2,5263.43 U21.1@4996.74,5257.97 ; U17.9@4851.2,5281.73 4874.95,5257.97 U21.1@4996.74,5257.97
RJ1A: RJ1.4 U2.23 | length 847
  Top Layer w10: RJ1.4@4080.04,5640.91 4170.91,5640.91 4319.82,5789.82 4325,5784.64 4325,5770 4190,5635 4190,5625 4195,5620 4205,5620 v2(4265,5680) ; v2(4340,5610) 4442.6,5610 U2.23@4452.6,5600
  Bottom Layer w10: v2(4265,5680) 4270,5680 v2(4340,5610)
RJ1B: RJ1.5 U2.22 | length 856
  Top Layer w10: RJ1.5@4009.96,5681.07 3925,5596.12 3925,5515 3949.13,5490.87 3950.52,5490.87 3997.32,5444.08 3997.32,5442.68 4010,5430 4110,5430 4330,5650 U2.22@4452.6,5650
RJ2A: RJ1.1 U2.20 | length 546
  Top Layer w10: RJ1.1@4009.96,5520.44 4019.95,5510.44 4153.05,5510.44 4366.27,5723.66 4426.26,5723.66 U2.20@4452.6,5750
RJ2B: RJ1.2 U2.19 | length 539.9
  Top Layer w10: RJ1.2@4080.04,5560.6 4085.63,5555 4140,5555 4155,5570 4155,5594.59 ; 4157.46,5597.05 4162.7,5602.3 4170,5595 4170,5565 4175,5560 4180,5560 4420,5800 U2.19@4452.6,5800
RJ3A: RJ1.3 U2.17 | length 744.8
  Top Layer w10: v2(4375,5885) 4437.6,5885 U2.17@4452.6,5900
  Bottom Layer w10: RJ1.3@4009.96,5600.76 4009.95,5620.99 3967.47,5663.47 3967.47,5802.47 4050,5885 v2(4375,5885)
RJ3B: RJ1.6 U2.16 | length 734.9
  Top Layer w10: RJ1.6@4080.04,5721.23 4125,5766.2 4125,5854.14 4130.86,5860 4139.14,5860 4145,5854.14 4145,5740 4152.07,5732.93 4237.93,5732.93 4345,5840 4345,5915 4380,5950 U2.16@4452.6,5950
RJ4A: RJ1.7 U2.14 | length 674.7
  Top Layer w10: v2(4060,5860) 4030.98,5889.02 4030.98,5933.38 4076.62,5979.02 4311.62,5979.02 4382.61,6050 U2.14@4452.6,6050
  Bottom Layer w10: RJ1.7@4009.96,5761.39 4009.95,5809.95 v2(4060,5860)
RJ4B: RJ1.8 U2.13 | length 669.3
  Top Layer w10: RJ1.8@4080.04,5801.54 4015,5866.57 4015,5940 4070,5995 4305,5995 4410,6100 U2.13@4452.6,6100
RST: C74.1 D35.2 R36.2 SW1.4 U3.29 U12.37 U27.5 | length 6423.7
  Top Layer w10: C74.1@4649.16,4855 4649.16,4879.16 4712.74,4942.74 ; v1(4712.74,4565) v1(4712.74,4645) ; v1(4712.74,4895) 4712.74,4942.74 ; v1(5275,3975) 5289.65,3960.35 SW1.4@5289.65,3923.58 ; U12.37@5603.27,6077.32 5632.68,6077.32 v1(5640,6070) ; D35.2@5683.07,5415 5628.07,5360 ; v1(6035,5360) 5981.75,5360 U3.29@5977.5,5364.25 5973.25,5360 5628.07,5360 ; U27.5@6240,6105 6293.57,6051.43 6359.23,6051.43 6386.43,6024.23 6386.43,5934.77 6357.34,5905.67 6357.34,5798.34 6363.78,5791.89 6417.48,5791.89 6423.92,5798.34 6423.92,5832.89 6438.55,5847.51 6451.86,5847.51 R36.2@6469.37,5830 ; 4712.74,4942.74 4810,5040 5400,5040 5425,5065 5425,5185 5600,5360 5628.07,5360
  Bottom Layer w10: v1(4712.74,4565) 5023.58,4254.16 5023.58,4020.47 5037.05,4007 5243,4007 v1(5275,3975) ; v1(4712.74,4645) v1(4712.74,4895) ; v1(5640,6070) 5665,6045 5665,5941.53 5625,5901.53 5526.73,5901.53 5431,5805.8 5431,5613.53 5421,5603.53 5421,5470.48 5365.04,5414.53 5365.04,5395.47 5378.52,5382 5397.57,5382 5411.04,5395.47 5411.04,5408.2 5494.84,5492 5499.53,5492 5550.33,5542.8 5550.33,5635.33 5667,5752 5716.55,5752 ; v1(6035,5360) 6035,5433.55 5716.55,5752 ; U27.5@6240,6105 6020,6105 5995.34,6080.34 5995.34,6030.79 5716.55,5752
SCLK: U3.17 U12.33 U27.3 | length 1648.9
  Top Layer w10: U12.33@5662.32,5959.21 5689.92,5959.21 5698.97,5968.27 6133.5,5968.27 6300,5801.77 6300,5569.72 6287.28,5557 6287.28,5552 ; U3.17@6260.24,5552 6287.28,5552 ; v1(6285,5525) 6285,5549.72 6287.28,5552
  Bottom Layer w10: v1(6285,5525) 6285,5585.2 6254,5616.2 6254,5710.93 6293.57,5750.49 6293.57,6024.23 6340,6070.67 U27.3@6340,6105
W5500CS: U3.14 U12.32 | length 1159.3
  Top Layer w10: U12.32@5662.32,5939.53 5690.03,5939.53 5704.77,5954.27 6127.71,5954.27 6286,5795.97 6286,5639 v1(6277,5630) ; U3.14@6322.5,5427.24 6325.26,5430 v1(6375,5430)
  Bottom Layer w10: v1(6277,5630) 6375,5532 v1(6375,5430)
W5500INT: U12.36
XTAL1: C46.2 U3.7 X1.1 | length 647.1
  Top Layer w10: U3.7@6228.74,5208 6240.38,5196.36 6240.38,5176.15 6252.01,5164.52 6414.32,5164.52 6537.16,5287.36 6537.16,5333.16 X1.1@6559.75,5355.75 6559.75,5214.52 C46.2@6587.28,5186.99
XTAL2: C45.1 U3.8 X1.2 | length 910
  Top Layer w10: U3.8@6260.24,5208 6438,5208 6523.16,5293.16 6523.16,5468.57 6559.75,5505.16 X1.2@6559.75,5714.25 6587.28,5741.78 C45.1@6587.28,5878.41
pads on no net: SW1.2 SW1.3 U2.1 U2.4 U2.7 U2.10 U12.7 U12.12 U12.13 U12.18 U12.24 U12.26 U12.38 U12.39 U12.40 U12.41 U12.42 U12.46 U12.47 U25.5 U25.6 U25.7 U31.9 U31.10 U31.11 U31.12 U31.14 U31.15 U32.7 U35.7 U39.7 U42.7 U46.7 U51.12 U51.13 U55.12 U55.13 USB1.A2 USB1.A3 USB1.A4 USB1.A8 USB1.A9 USB1.A10 USB1.A11 USB1.B2 USB1.B3 USB1.B4 USB1.B8 USB1.B9 USB1.B10 USB1.B11

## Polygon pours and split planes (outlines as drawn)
AGND on Top Layer (solid, remove dead copper, pour order 0): 3620,6290 7235,6290 7235,3095 3620,3095
AGND on Bottom Layer (solid, remove dead copper, pour order 4): 3620,6300 7265,6300 7265,3010 3620,3010
AGND on Top Layer (solid, remove dead copper, pour order 2): 3530,6350 7455,6350 7455,3000 3530,3000

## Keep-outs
Board Outline Layer:
  circle w10: c7075,6135 r59.06
  circle w10: c7075,3235 r59.06
  circle w10: c3775,6135 r59.06
  circle w10: c3775,3235 r59.1
  lines w10: 3675,3135 7175,3135 7175,6235 3675,6235 3675,3135

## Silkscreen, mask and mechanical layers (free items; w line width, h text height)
Top Silkscreen Layer:
  text "ICSP" at 6195,6165 h60
  text "0  1  2" at 5759.25,6159.22 h60
  text "5V /  3.3V" at 6760,6045 h50
  text "LNK SPD" at 5755,5950 h60
  text "GND" at 6180,5890 h60
  text "GND   DIR   PWM  ACT0" at 7160,5415 h50 r90
  text "POE OK" at 4020,5280 h50
  text "ACT1 GND   DIR   PWM" at 7160,4685 h50 r90
  text "OCTET SELECT" at 3755,4145 h40 r90
  text "RST" at 5350,3940 h120
  text "ACT0  GND     B     A     5V" at 4565,3155 h50
  text "GND     B     A     5V  ACT1" at 5590,3155 h50
Bottom Silkscreen Layer:
  text "University Of Akron /  RMC Team /  2025" at 4550.2,5983.66 h40
  text "ACT 0 RET   EXT   GND" at 7053.39,4804.51 h50 r90
  text "Limit Switches Are Pulldown Contacts /  Common Cathode" at 6865,4390 h40 r90
  text "Lane Cline /  Eli Bukoski /  Garren Ward /  Jonathan Donley /  Alex Kinch /  Tatsuya Wachtl /  William Forcey /  Ethan Banning /  Seth McCord /  Logan Foster /  Zane Nold /  Liam Boich" at 6020,3970 h40
  text "RET   EXT   GND ACT1" at 7050,3955 h50 r90
  text "Dual Encoder Actuator Module    REV 1" at 6595,3190 h120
